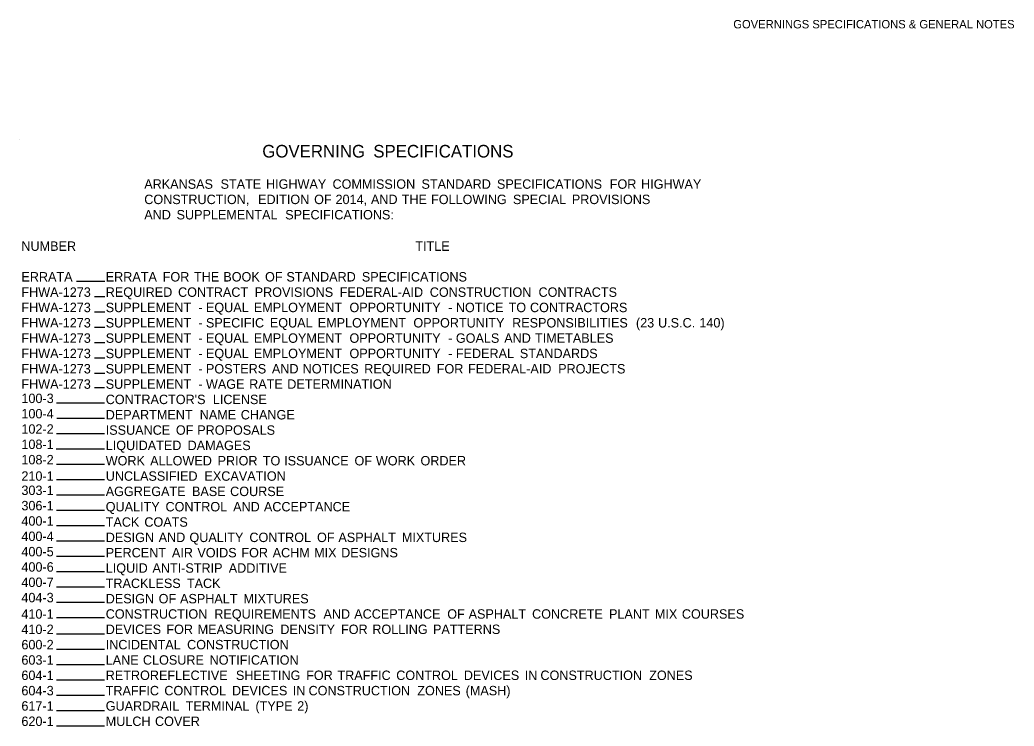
# Model space of a CAD drawing. Extents: x 1930579 to 1932220, y 596452 to 599479.
# Drawn here: x 1931524 to 1932220, y 598985 to 599479 of the extents above; entities that cross this region are included whole.
import ezdxf

# ---------------------------------------------------------------- set-up
doc = ezdxf.new("R2010")
doc.units = 0
for name, color, linetype in [('Default', 7, 'Continuous'), ('R_Border', 7, 'Continuous'), ('R_Border Prem', 7, 'Continuous')]:
    doc.layers.add(name, color=color, linetype=linetype)

msp = doc.modelspace()

# ---------------------------------------------------------------- linework, layer by layer
at = {"layer": 'R_Border'}
for p, q in [((1931524.27, 599395.37), (1931524.27, 599395.37)), ((1931563.85, 599296.07), (1931583.71, 599296.07)), ((1931576.5, 599285.34), (1931583.71, 599285.34)), ((1931576.5, 599274.62), (1931583.71, 599274.62)), ((1931576.5, 599263.89), (1931583.71, 599263.89)), ((1931576.5, 599253.17), (1931583.71, 599253.17)), ((1931576.5, 599242.44), (1931583.71, 599242.44)), ((1931576.5, 599231.72), (1931583.71, 599231.72)), ((1931576.5, 599221.73), (1931583.53, 599221.73)), ((1931549.9, 599211.01), (1931583.53, 599211.01)), ((1931550.12, 599200.28), (1931583.53, 599200.28)), ((1931549.9, 599189.56), (1931583.53, 599189.56)), ((1931549.66, 599178.83), (1931583.53, 599178.83)), ((1931549.9, 599168.11), (1931583.53, 599168.11)), ((1931549.9, 599157.38), (1931583.53, 599157.38)), ((1931549.9, 599146.66), (1931583.53, 599146.66)), ((1931549.9, 599135.93), (1931583.53, 599135.93)), ((1931549.9, 599125.21), (1931583.53, 599125.21)), ((1931549.9, 599114.48), (1931583.53, 599114.48)), ((1931549.9, 599103.76), (1931583.53, 599103.76)), ((1931549.9, 599093.03), (1931583.53, 599093.03)), ((1931549.9, 599082.31), (1931583.53, 599082.31)), ((1931549.9, 599071.58), (1931583.53, 599071.58)), ((1931549.9, 599060.86), (1931583.53, 599060.86)), ((1931549.9, 599049.39), (1931583.53, 599049.39)), ((1931549.9, 599038.67), (1931583.53, 599038.67)), ((1931549.9, 599027.94), (1931583.53, 599027.94)), ((1931549.9, 599017.22), (1931583.53, 599017.22)), ((1931549.9, 599006.49), (1931583.53, 599006.49)), ((1931549.9, 598995.77), (1931583.53, 598995.77)), ((1931549.9, 598985.04), (1931583.53, 598985.04))]:
    msp.add_line(p, q, dxfattribs=at)

# ---------------------------------------------------------------- texts
at = {"layer": 'Default'}
for s, height, p in [('GOVERNING', 8.8, (1931693.89, 599382.66)), (' SPECIFICATIONS', 8.8, (1931768.3, 599382.66)), ('           ARKANSAS', 6.6, (1931584.33, 599360.77)), (' STATE', 6.6, (1931662.24, 599360.77)), (' HIGHWAY', 6.6, (1931694.04, 599360.77)), (' COMMISSION', 6.6, (1931740.59, 599360.77)), (' STANDARD', 6.6, (1931802.85, 599360.77)), (' SPECIFICATIONS', 6.6, (1931855.65, 599360.77)), (' FOR', 6.6, (1931934.59, 599360.77)), (' HIGHWAY', 6.6, (1931956.5, 599360.77)), ('           CONSTRUCTION,', 6.6, (1931584.33, 599350.04)), (' EDITION', 6.6, (1931688.52, 599350.04)), (' OF', 6.6, (1931727.73, 599350.04)), (' 2014,', 6.6, (1931742.68, 599350.04)), (' AND', 6.6, (1931767.48, 599350.04)), (' THE', 6.6, (1931789.02, 599350.04)), (' FOLLOWING', 6.6, (1931809.54, 599350.04)), (' SPECIAL', 6.6, (1931866.85, 599350.04)), (' PROVISIONS', 6.6, (1931908.04, 599350.04)), ('           AND', 6.6, (1931584.33, 599339.32)), (' SUPPLEMENTAL', 6.6, (1931631.47, 599339.32)), (' SPECIFICATIONS:', 6.6, (1931707.51, 599339.32)), ('NUMBER', 6.6, (1931525.34, 599317.33)), ('TITLE', 6.6, (1931800.99, 599317.33)), ('ERRATA', 6.6, (1931525.34, 599295.88)), ('ERRATA', 6.6, (1931584.33, 599295.88)), (' FOR', 6.6, (1931621.75, 599295.88)), (' THE', 6.6, (1931643.66, 599295.88)), (' BOOK', 6.6, (1931664.17, 599295.88)), (' OF', 6.6, (1931693.36, 599295.88)), (' STANDARD', 6.6, (1931708.31, 599295.88)), (' SPECIFICATIONS', 6.6, (1931761.11, 599295.88)), ('FHWA-1273', 6.6, (1931525.34, 599285.15)), ('REQUIRED', 6.6, (1931584.33, 599285.15)), (' CONTRACT', 6.6, (1931632.51, 599285.15)), (' PROVISIONS', 6.6, (1931686.12, 599285.15)), (' FEDERAL-AID', 6.6, (1931745.6, 599285.15)), (' CONSTRUCTION', 6.6, (1931808.65, 599285.15)), (' CONTRACTS', 6.6, (1931884.74, 599285.15)), ('FHWA-1273', 6.6, (1931525.34, 599274.43)), ('SUPPLEMENT', 6.6, (1931584.33, 599274.43)), (' -', 6.6, (1931646.66, 599274.43)), (' EQUAL', 6.6, (1931652.01, 599274.43)), (' EMPLOYMENT', 6.6, (1931685.51, 599274.43)), (' OPPORTUNITY', 6.6, (1931752.45, 599274.43)), (' -', 6.6, (1931821.55, 599274.43)), (' NOTICE', 6.6, (1931826.89, 599274.43)), (' TO', 6.6, (1931863.8, 599274.43)), (' CONTRACTORS', 6.6, (1931878.76, 599274.43)), ('FHWA-1273', 6.6, (1931525.34, 599263.7)), ('SUPPLEMENT', 6.6, (1931584.33, 599263.7)), (' SPECIFIC', 6.6, (1931652.01, 599263.7)), (' EQUAL', 6.6, (1931696.73, 599263.7)), (' EMPLOYMENT', 6.6, (1931730.23, 599263.7)), (' OPPORTUNITY', 6.6, (1931797.17, 599263.7)), (' RESPONSIBILITIES', 6.6, (1931866.28, 599263.7)), (' (23', 6.6, (1931952.92, 599263.7)), (' U.S.C.', 6.6, (1931968.38, 599263.7)), (' 140)', 6.6, (1931997.29, 599263.7)), (' -', 6.6, (1931646.66, 599263.7)), ('FHWA-1273', 6.6, (1931525.34, 599252.98)), ('SUPPLEMENT', 6.6, (1931584.33, 599252.98)), (' EQUAL', 6.6, (1931652.01, 599252.98)), (' EMPLOYMENT', 6.6, (1931685.51, 599252.98)), (' OPPORTUNITY', 6.6, (1931752.45, 599252.98)), (' GOALS', 6.6, (1931826.89, 599252.98)), (' AND', 6.6, (1931860.75, 599252.98)), (' TIMETABLES', 6.6, (1931882.29, 599252.98)), (' -', 6.6, (1931646.66, 599252.98)), (' -', 6.6, (1931821.55, 599252.98)), ('FHWA-1273', 6.6, (1931525.34, 599242.25)), ('SUPPLEMENT', 6.6, (1931584.33, 599242.25)), (' -', 6.6, (1931646.66, 599242.25)), (' EQUAL', 6.6, (1931652.01, 599242.25)), (' EMPLOYMENT', 6.6, (1931685.51, 599242.25)), (' OPPORTUNITY', 6.6, (1931752.45, 599242.25)), (' -', 6.6, (1931821.55, 599242.25)), (' FEDERAL', 6.6, (1931826.89, 599242.25)), (' STANDARDS', 6.6, (1931871.66, 599242.25)), ('FHWA-1273', 6.6, (1931525.34, 599231.53)), ('SUPPLEMENT', 6.6, (1931584.33, 599231.53)), (' POSTERS', 6.6, (1931652.01, 599231.53)), (' AND', 6.6, (1931698.16, 599231.53)), (' NOTICES', 6.6, (1931719.7, 599231.53)), (' REQUIRED', 6.6, (1931762.77, 599231.53)), (' FOR', 6.6, (1931813.52, 599231.53)), (' FEDERAL-AID', 6.6, (1931835.42, 599231.53)), (' PROJECTS', 6.6, (1931898.47, 599231.53)), (' -', 6.6, (1931646.66, 599231.53)), ('FHWA-1273', 6.6, (1931525.34, 599220.8)), ('SUPPLEMENT', 6.6, (1931584.33, 599220.8)), (' -', 6.6, (1931646.66, 599220.8)), (' WAGE', 6.6, (1931652.01, 599220.8)), (' RATE', 6.6, (1931682.26, 599220.8)), (' DETERMINATION', 6.6, (1931708.92, 599220.8)), ('100-3', 6.6, (1931525.34, 599210.82)), ("CONTRACTOR'S", 6.6, (1931584.33, 599210.08)), (' LICENSE', 6.6, (1931656.83, 599210.08)), ('100-4', 6.6, (1931525.34, 599200.1)), ('DEPARTMENT', 6.6, (1931584.33, 599199.35)), (' NAME', 6.6, (1931647.68, 599199.35)), (' CHANGE', 6.6, (1931676.39, 599199.35)), ('102-2', 6.6, (1931525.34, 599189.37)), ('ISSUANCE', 6.6, (1931584.33, 599188.63)), (' OF', 6.6, (1931630.98, 599188.63)), (' PROPOSALS', 6.6, (1931645.93, 599188.63)), ('108-1', 6.6, (1931525.34, 599178.65)), ('LIQUIDATED', 6.6, (1931584.33, 599177.9)), (' DAMAGES', 6.6, (1931639.17, 599177.9)), ('108-2', 6.6, (1931525.34, 599167.92)), ('WORK', 6.6, (1931584.33, 599167.18)), (' ALLOWED', 6.6, (1931613, 599167.18)), (' PRIOR', 6.6, (1931660.16, 599167.18)), (' TO', 6.6, (1931691.8, 599167.18)), (' ISSUANCE', 6.6, (1931706.75, 599167.18)), (' OF', 6.6, (1931755.97, 599167.18)), (' WORK', 6.6, (1931770.92, 599167.18)), (' ORDER', 6.6, (1931802.15, 599167.18)), ('210-1', 6.6, (1931525.34, 599156.45)), ('UNCLASSIFIED', 6.6, (1931584.33, 599156.45)), (' EXCAVATION', 6.6, (1931650.97, 599156.45)), ('303-1', 6.6, (1931525.34, 599146.47)), ('AGGREGATE', 6.6, (1931584.33, 599145.73)), (' BASE', 6.6, (1931642.26, 599145.73)), (' COURSE', 6.6, (1931668.93, 599145.73)), ('306-1', 6.6, (1931525.34, 599135.75)), ('QUALITY', 6.6, (1931584.33, 599135)), (' CONTROL', 6.6, (1931623.72, 599135)), (' AND', 6.6, (1931671.04, 599135)), (' ACCEPTANCE', 6.6, (1931692.58, 599135)), ('400-1', 6.6, (1931525.34, 599125.02)), ('TACK', 6.6, (1931584.33, 599124.28)), (' COATS', 6.6, (1931608.91, 599124.28)), ('400-4', 6.6, (1931525.34, 599114.3)), ('DESIGN', 6.6, (1931584.33, 599113.55)), (' AND', 6.6, (1931618.93, 599113.55)), (' QUALITY', 6.6, (1931640.47, 599113.55)), (' CONTROL', 6.6, (1931682.42, 599113.55)), (' OF', 6.6, (1931729.74, 599113.55)), (' ASPHALT', 6.6, (1931744.69, 599113.55)), (' MIXTURES', 6.6, (1931789.09, 599113.55)), ('400-5', 6.6, (1931525.34, 599103.57)), ('PERCENT', 6.6, (1931584.33, 599102.83)), (' AIR', 6.6, (1931628.21, 599102.83)), (' VOIDS', 6.6, (1931646.02, 599102.83)), (' FOR', 6.6, (1931676.8, 599102.83)), (' ACHM', 6.6, (1931698.7, 599102.83)), (' MIX', 6.6, (1931727.72, 599102.83)), (' DESIGNS', 6.6, (1931746.62, 599102.83)), ('400-6', 6.6, (1931525.34, 599092.85)), ('LIQUID', 6.6, (1931584.33, 599092.1)), (' ANTI-STRIP', 6.6, (1931614.58, 599092.1)), (' ADDITIVE', 6.6, (1931667.97, 599092.1)), ('400-7', 6.6, (1931525.34, 599082.12)), ('TRACKLESS', 6.6, (1931584.33, 599081.38)), (' TACK', 6.6, (1931638.69, 599081.38)), ('404-3', 6.6, (1931525.34, 599071.4)), ('DESIGN', 6.6, (1931584.33, 599070.65)), (' OF', 6.6, (1931618.93, 599070.65)), (' ASPHALT', 6.6, (1931633.88, 599070.65)), (' MIXTURES', 6.6, (1931678.28, 599070.65)), ('410-1', 6.6, (1931525.34, 599059.93)), ('CONSTRUCTION', 6.6, (1931584.33, 599059.93)), (' REQUIREMENTS', 6.6, (1931657.86, 599059.93)), (' AND', 6.6, (1931734.24, 599059.93)), (' ACCEPTANCE', 6.6, (1931755.78, 599059.93)), (' OF', 6.6, (1931820.89, 599059.93)), (' ASPHALT', 6.6, (1931835.83, 599059.93)), (' CONCRETE', 6.6, (1931880.24, 599059.93)), (' PLANT', 6.6, (1931934.06, 599059.93)), (' MIX', 6.6, (1931966.16, 599059.93)), (' COURSES', 6.6, (1931985.05, 599059.93)), ('410-2', 6.6, (1931525.34, 599049.2)), ('DEVICES', 6.6, (1931584.33, 599049.2)), (' FOR', 6.6, (1931624.33, 599049.2)), (' MEASURING', 6.6, (1931646.24, 599049.2)), (' DENSITY', 6.6, (1931704.07, 599049.2)), (' FOR', 6.6, (1931746.53, 599049.2)), (' ROLLING', 6.6, (1931768.44, 599049.2)), (' PATTERNS', 6.6, (1931810.9, 599049.2)), ('600-2', 6.6, (1931525.34, 599038.48)), ('INCIDENTAL', 6.6, (1931584.33, 599038.48)), (' CONSTRUCTION', 6.6, (1931638.83, 599038.48)), ('603-1', 6.6, (1931525.34, 599027.75)), ('LANE', 6.6, (1931584.33, 599027.75)), (' CLOSURE', 6.6, (1931607.92, 599027.75)), (' NOTIFICATION', 6.6, (1931654.58, 599027.75)), ('604-1', 6.6, (1931525.34, 599017.03)), ('RETROREFLECTIVE', 6.6, (1931584.33, 599017.03)), (' SHEETING', 6.6, (1931673, 599017.03)), (' FOR', 6.6, (1931722.13, 599017.03)), (' TRAFFIC', 6.6, (1931744.03, 599017.03)), (' CONTROL', 6.6, (1931785.16, 599017.03)), (' DEVICES', 6.6, (1931832.48, 599017.03)), (' IN', 6.6, (1931875.05, 599017.03)), (' CONSTRUCTION', 6.6, (1931886.08, 599017.03)), (' ZONES', 6.6, (1931962.17, 599017.03)), ('604-3', 6.6, (1931525.34, 599006.3)), ('TRAFFIC', 6.6, (1931584.33, 599006.3)), (' CONTROL', 6.6, (1931622.9, 599006.3)), (' DEVICES', 6.6, (1931670.22, 599006.3)), (' CONSTRUCTION', 6.6, (1931723.81, 599006.3)), (' ZONES', 6.6, (1931799.91, 599006.3)), (' (MASH)', 6.6, (1931833.76, 599006.3)), (' IN', 6.6, (1931712.79, 599006.3)), ('617-1', 6.6, (1931525.34, 598995.58)), ('GUARDRAIL', 6.6, (1931584.33, 598995.58)), (' TERMINAL', 6.6, (1931637.81, 598995.58)), (' (TYPE', 6.6, (1931686.67, 598995.58)), (' 2)', 6.6, (1931715.89, 598995.58)), ('620-1', 6.6, (1931525.34, 598984.85)), ('MULCH', 6.6, (1931584.33, 598984.85)), (' COVER', 6.6, (1931616.37, 598984.85))]:
    msp.add_text(s, height=height, dxfattribs=at).set_placement(p)
at = {"layer": 'R_Border Prem'}
msp.add_text('GOVERNINGS SPECIFICATIONS & GENERAL NOTES', height=5.862, rotation=360, dxfattribs=at).set_placement((1932023.47, 599473))

doc.saveas('drawing.dxf')
